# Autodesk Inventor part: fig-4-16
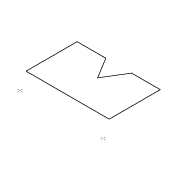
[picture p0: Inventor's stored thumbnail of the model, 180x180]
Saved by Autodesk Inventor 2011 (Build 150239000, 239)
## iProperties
Created: 2005-02
Part Number: fig-4-16
Document SubType Name: Modeling
Designer: CADCIM
Manufacturer: Standard
Standards Organization: Custom
Density: 1 g/cm^3
Author: CADCIM
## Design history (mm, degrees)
sketch "Sketch1"
  geometry: L1 (-25.19, 27.524)-(-25.19, 5.557); L2 (-25.19, 5.557)-(10.567, 5.557); L3 (10.567, 5.557)-(10.567, 27.524); L4 (10.567, 27.524)-(-1.76, 27.524); L5 (-1.76, 27.524)-(-7.312, 18.449); L6 (-7.312, 18.449)-(-12.863, 27.524); L7 (-12.863, 27.524)-(-25.19, 27.524); 2 further points
  constraints: 14 end point, 3 equal length, 3 parallel, 1 perpendicular, 1 vertical, 1 other
